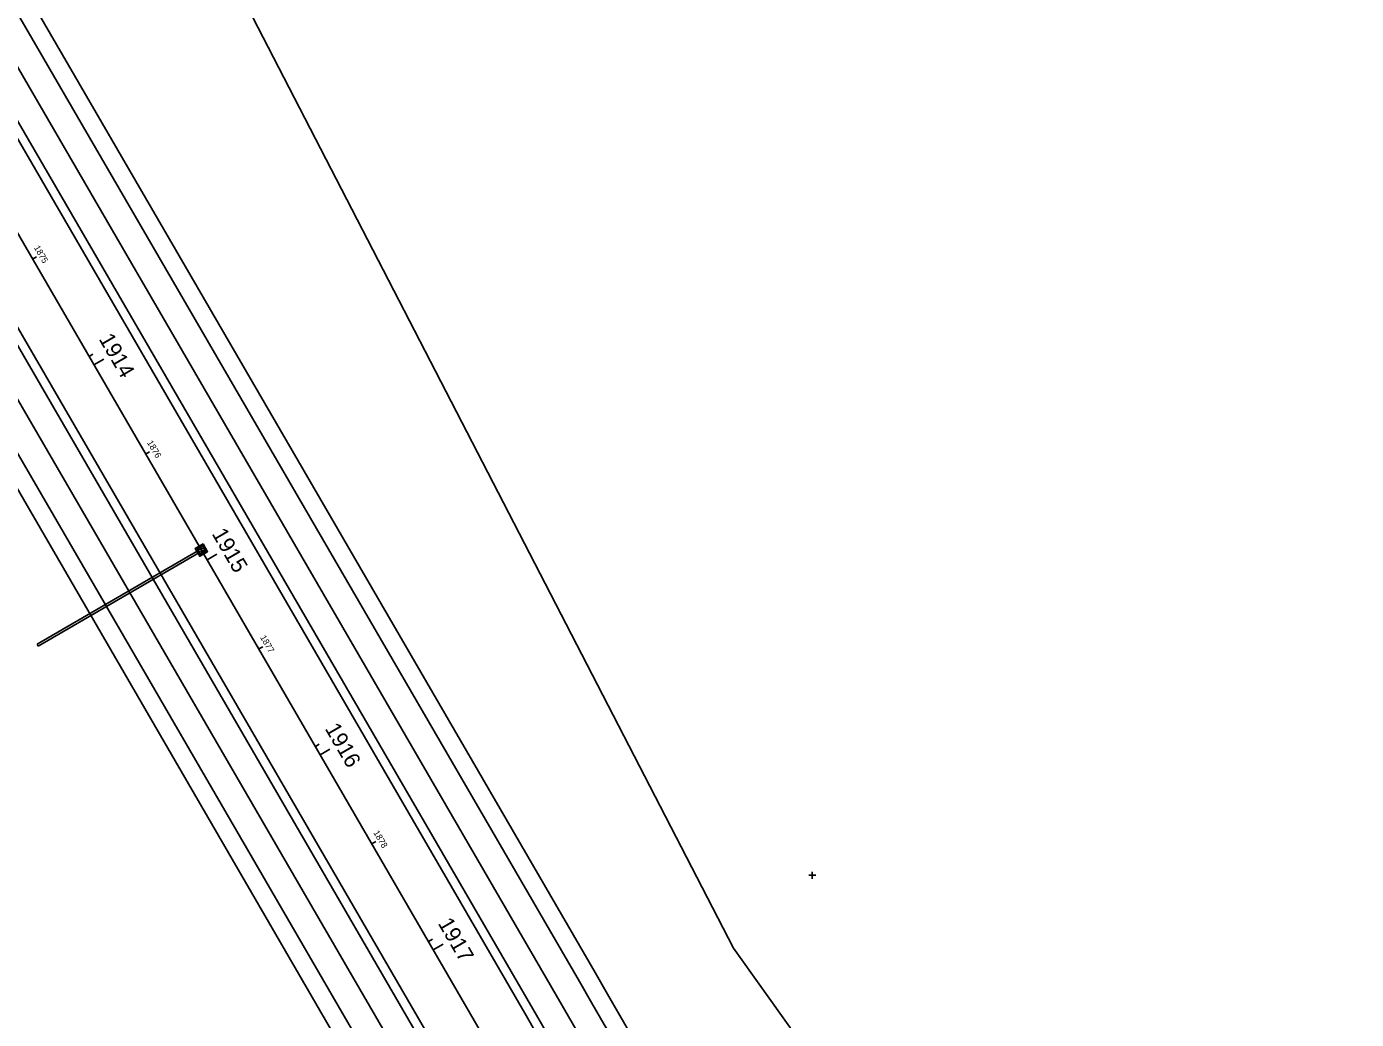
# Model space of a CAD drawing. Extents: x 6334 to 41599, y 9030 to 59113.
# Drawn here: x 23757 to 24347, y 29060 to 29500 of the extents above; entities that cross this region are included whole.
import ezdxf

# ---------------------------------------------------------------- set-up
doc = ezdxf.new("R2010")
doc.units = 0
for name, color, linetype in [('DR_X_Cells', 7, 'Continuous'), ('DR_X_Culvert', 7, 'Continuous'), ('GE_X_CL_20', 7, 'Continuous'), ('GE_X_CL_50', 7, 'Continuous'), ('GK_Drainage_Nodes', 7, 'Continuous'), ('GK_Visualization', 7, 'Continuous'), ('PM_X_Lane_Line', 7, 'Continuous'), ('PV_X_EOP', 7, 'Continuous'), ('PV_X_Shoulder', 7, 'Continuous'), ('RW_X_Esmt_LA', 7, 'Continuous')]:
    doc.layers.add(name, color=color, linetype=linetype)

msp = doc.modelspace()

# ---------------------------------------------------------------- linework, layer by layer
at = {"layer": 'DR_X_Cells'}
for p, q in [((23832.38, 29268.38), (23836.03, 29267.41)), ((23832.6, 29267.5), (23835.05, 29266.84)), ((23833.16, 29266.52), (23834.07, 29266.28)), ((23833.36, 29268.95), (23835.87, 29268.28)), ((23834.34, 29269.52), (23835.31, 29269.26))]:
    msp.add_line(p, q, dxfattribs=at)
for points in [[(23834.95, 29270.64), (23836.96, 29267.18), (23833.5, 29265.17), (23831.49, 29268.63)], [(23834.95, 29269.87), (23836.29, 29267.56), (23833.5, 29265.94), (23832.16, 29268.25)], [(23834.71, 29269.73), (23836.05, 29267.42), (23833.74, 29266.08), (23832.4, 29268.39)]]:
    msp.add_lwpolyline(points, close=True, dxfattribs=at)
at = {"layer": 'DR_X_Culvert'}
for p, q in [((23761.32, 29226.19), (23832.58, 29267.53)), ((23761.82, 29225.32), (23833.08, 29266.66)), ((23761.32, 29226.19), (23761.82, 29225.32))]:
    msp.add_line(p, q, dxfattribs=at)
at = {"layer": 'GE_X_CL_20'}
for p, q in [((23283.64, 30216.92), (23959.58, 29051.85)), ((23759.32, 29397.02), (23761.05, 29398.03)), ((23784.41, 29353.77), (23786.14, 29354.78)), ((23809.5, 29310.53), (23811.23, 29311.53)), ((23834.59, 29267.28), (23836.32, 29268.28)), ((23859.68, 29224.03), (23861.41, 29225.03)), ((23884.77, 29180.78), (23886.5, 29181.78)), ((23909.86, 29137.53), (23911.59, 29138.54)), ((23934.95, 29094.28), (23936.68, 29095.29))]:
    msp.add_line(p, q, dxfattribs=at)
at = {"layer": 'GE_X_CL_50'}
for p, q in [((23283.64, 30216.92), (23959.58, 29051.85)), ((23786.55, 29350.08), (23790.88, 29352.59)), ((23836.73, 29263.58), (23841.06, 29266.09)), ((23886.92, 29177.08), (23891.24, 29179.59)), ((23937.1, 29090.59), (23941.42, 29093.1))]:
    msp.add_line(p, q, dxfattribs=at)
at = {"layer": 'GK_Drainage_Nodes'}
for p, q in [((23832.5, 29266.9), (23832.5, 29266.9)), ((23832.83, 29267.1), (23832.83, 29267.1)), ((23833.07, 29267.24), (23833.07, 29267.24)), ((23833.56, 29269.06), (23833.56, 29269.06)), ((23834.22, 29267.91), (23834.22, 29267.91)), ((23834.22, 29267.91), (23834.22, 29267.91)), ((23834.89, 29266.75), (23834.89, 29266.75)), ((23835.38, 29268.58), (23835.38, 29268.58)), ((23835.95, 29268.91), (23835.95, 29268.91))]:
    msp.add_line(p, q, dxfattribs=at)
at = {"layer": 'GK_Visualization'}
for p, q in [((23283.64, 30216.92), (23959.58, 29051.85)), ((23283.64, 30216.92), (23959.58, 29051.85)), ((24106.73, 29123.62), (24103.61, 29123.62)), ((24105.17, 29125.18), (24105.17, 29122.06))]:
    msp.add_line(p, q, dxfattribs=at)
at = {"layer": 'PM_X_Lane_Line'}
for p, q in [((23315.65, 30235.48), (23991.58, 29070.41)), ((23251.64, 30198.35), (23927.57, 29033.28))]:
    msp.add_line(p, q, dxfattribs=at)
msp.add_arc((11569.81, 21863.73), 14360.94, 27.320833, 30.120833, dxfattribs=at)
at = {"layer": 'PV_X_EOP'}
for p, q in [((23326.03, 30241.51), (24001.96, 29076.43)), ((23305.27, 30229.46), (23981.2, 29064.39)), ((23262.02, 30204.37), (23937.95, 29039.3)), ((23241.26, 30192.33), (23917.19, 29027.26))]:
    msp.add_line(p, q, dxfattribs=at)
for radius in [14372.94, 14348.94]:
    msp.add_arc((11569.81, 21863.73), radius, 27.320833, 30.120833, dxfattribs=at)
at = {"layer": 'PV_X_Shoulder'}
for p, q in [((23332.95, 30245.52), (24008.88, 29080.45)), ((23301.81, 30227.45), (23977.74, 29062.38)), ((23265.48, 30206.38), (23941.41, 29041.31)), ((23234.34, 30188.31), (23910.27, 29023.24))]:
    msp.add_line(p, q, dxfattribs=at)
for radius in [14380.94, 14344.94]:
    msp.add_arc((11569.81, 21863.73), radius, 27.320833, 30.120833, dxfattribs=at)
at = {"layer": 'RW_X_Esmt_LA'}
msp.add_line((23823.78, 29568.81), (24070.22, 29091.36), dxfattribs=at)
msp.add_lwpolyline([(24070.22, 29091.36), (24208, 28898.05), (24303.2, 28793.52)], dxfattribs=at)

# ---------------------------------------------------------------- texts
at = {"layer": 'GE_X_CL_20'}
for s, p in [('1875', (23759.84, 29402.1)), ('1876', (23810.01, 29315.62)), ('1877', (23860.17, 29229.17)), ('1878', (23910.41, 29142.56))]:
    msp.add_text(s, height=2.8, rotation=300.12083, dxfattribs=at).set_placement(p)
at = {"layer": 'GE_X_CL_50'}
for s, p in [('1914', (23788.53, 29361.61)), ('1915', (23838.67, 29275.18)), ('1916', (23888.84, 29188.71)), ('1917', (23938.96, 29102.33))]:
    msp.add_text(s, height=7, rotation=300.12083, dxfattribs=at).set_placement(p)

doc.saveas('drawing.dxf')
